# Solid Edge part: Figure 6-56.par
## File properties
Author: Ashutosh-CADCIM
Template: Iso Metric Part.par
Last saved by: Ashutosh-CADCIM
Revision: 1
Application: Solid Edge
Accuracy: 0.990
Username: Ashutosh-CADCIM
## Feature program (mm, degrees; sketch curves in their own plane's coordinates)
sketch for "unnamed Protrusion 1" plane through (0, 0, 0) normal (0, 0, 1) x-axis (1, 0, 0)
  line (-125, -75) -> (125, -75)
  line (125, -75) -> (125, 75)
  line (125, 75) -> (-125, 75)
  line (-125, 75) -> (-125, -75)
  dimension (linear) = 125
  dimension (linear) = 125
extrude "unnamed Protrusion 1" add finite 30 symmetric
sketch for "unnamed Cutout 1" plane through (0, 0, 15) normal (0, 0, 1) x-axis (0, 1, 0)
  circle centre (59.8554, 100.6265) radius 10
extrude "unnamed Cutout 1" cut through along -normal
pattern "unnamed Pattern 1" of "unnamed Cutout 1"
pattern "Pattern_1" along a curve  XDirCount = 4; XDirSpacing = 40.9717 mm; YDirCount = 3; YDirSpacing = 100 mm
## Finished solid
Body 1: solid body, 18 faces, 36 edges, 8 vertices.
  Faces by surface: cylinder 12, plane 6
  Edges by curve: circle 24, line 12
Bounding box of the edges (mm): 250.000 x 150.000 x 30.000, from (-125, -75, -15) to (125, 75, 15).
Cylindrical faces by radius (mm): R10 x12
Planar faces by outward normal: +x 1, +y 1, +z 1, -x 1, -y 1, -z 1
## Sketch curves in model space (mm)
spline (-100.6265, -55.0843, 15) -> (-100.205, 1.4934, 15) -> (-100.6265, 59.8554, 15)
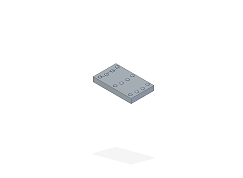
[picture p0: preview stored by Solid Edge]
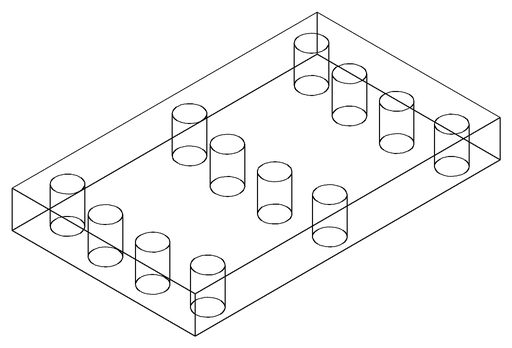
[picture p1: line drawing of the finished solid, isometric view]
